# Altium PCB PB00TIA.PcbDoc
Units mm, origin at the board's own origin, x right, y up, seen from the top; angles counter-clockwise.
Board outline 90 x 50 mm, 4 copper layers (Top Layer, PWR, GND, Bottom Layer), stack 0.603 mm thick; 69 components, 34 nets, 213 pads, 160 vias.
Unrouted connection lines stored in the file: 4.
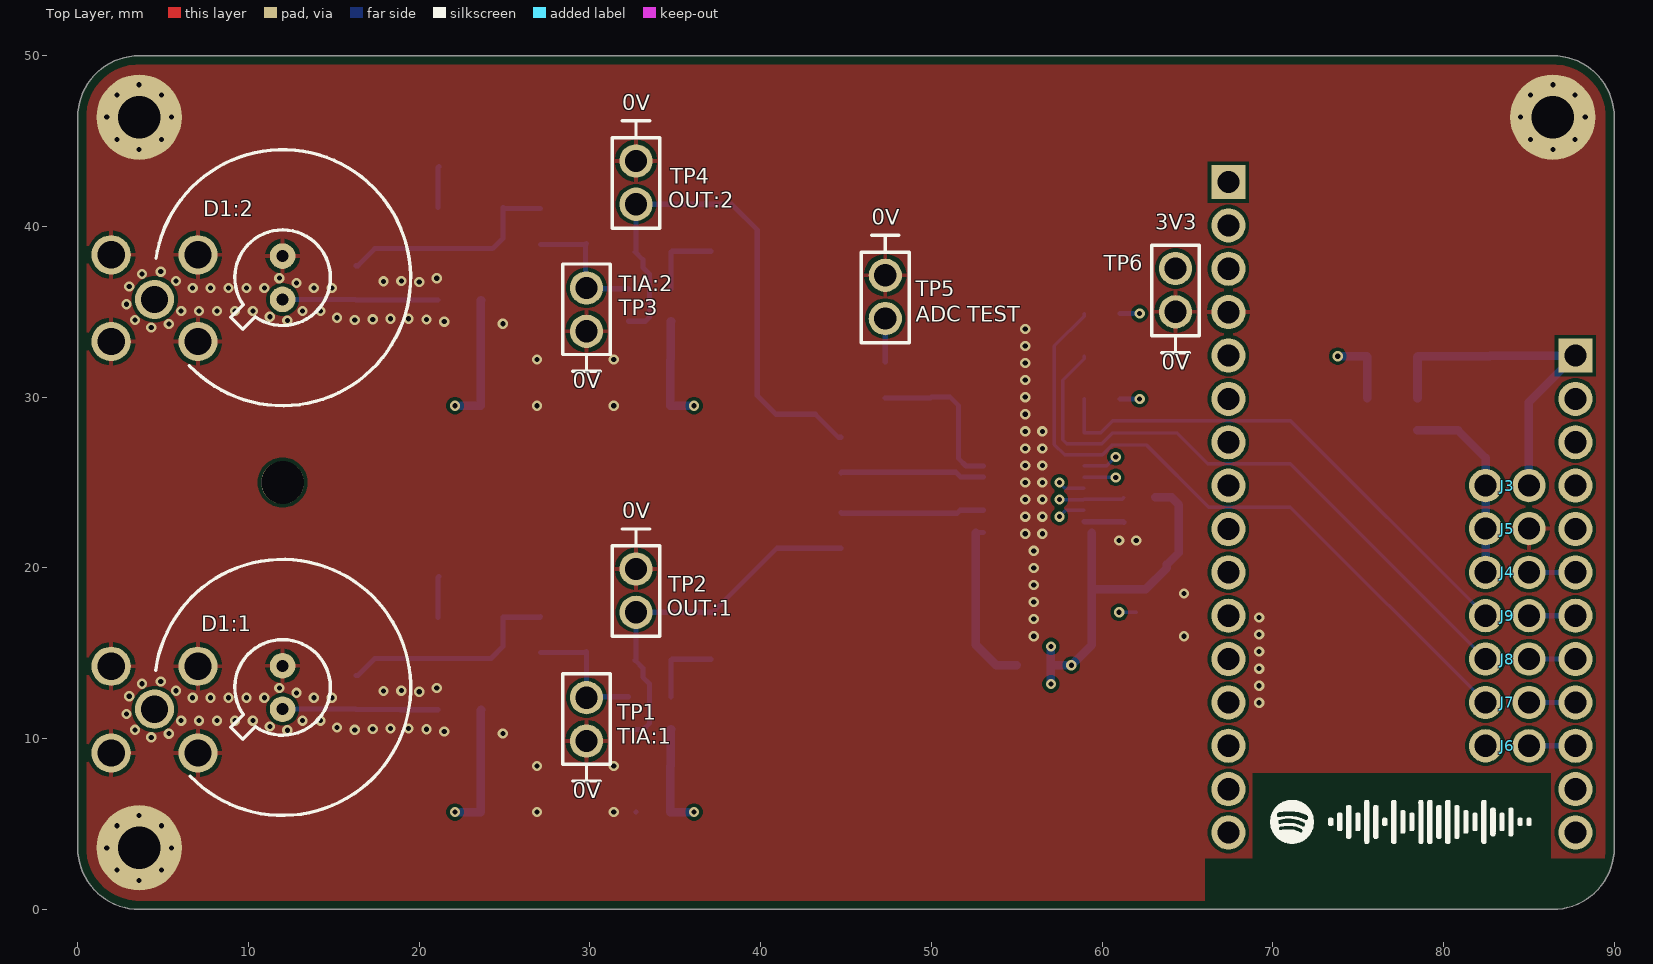
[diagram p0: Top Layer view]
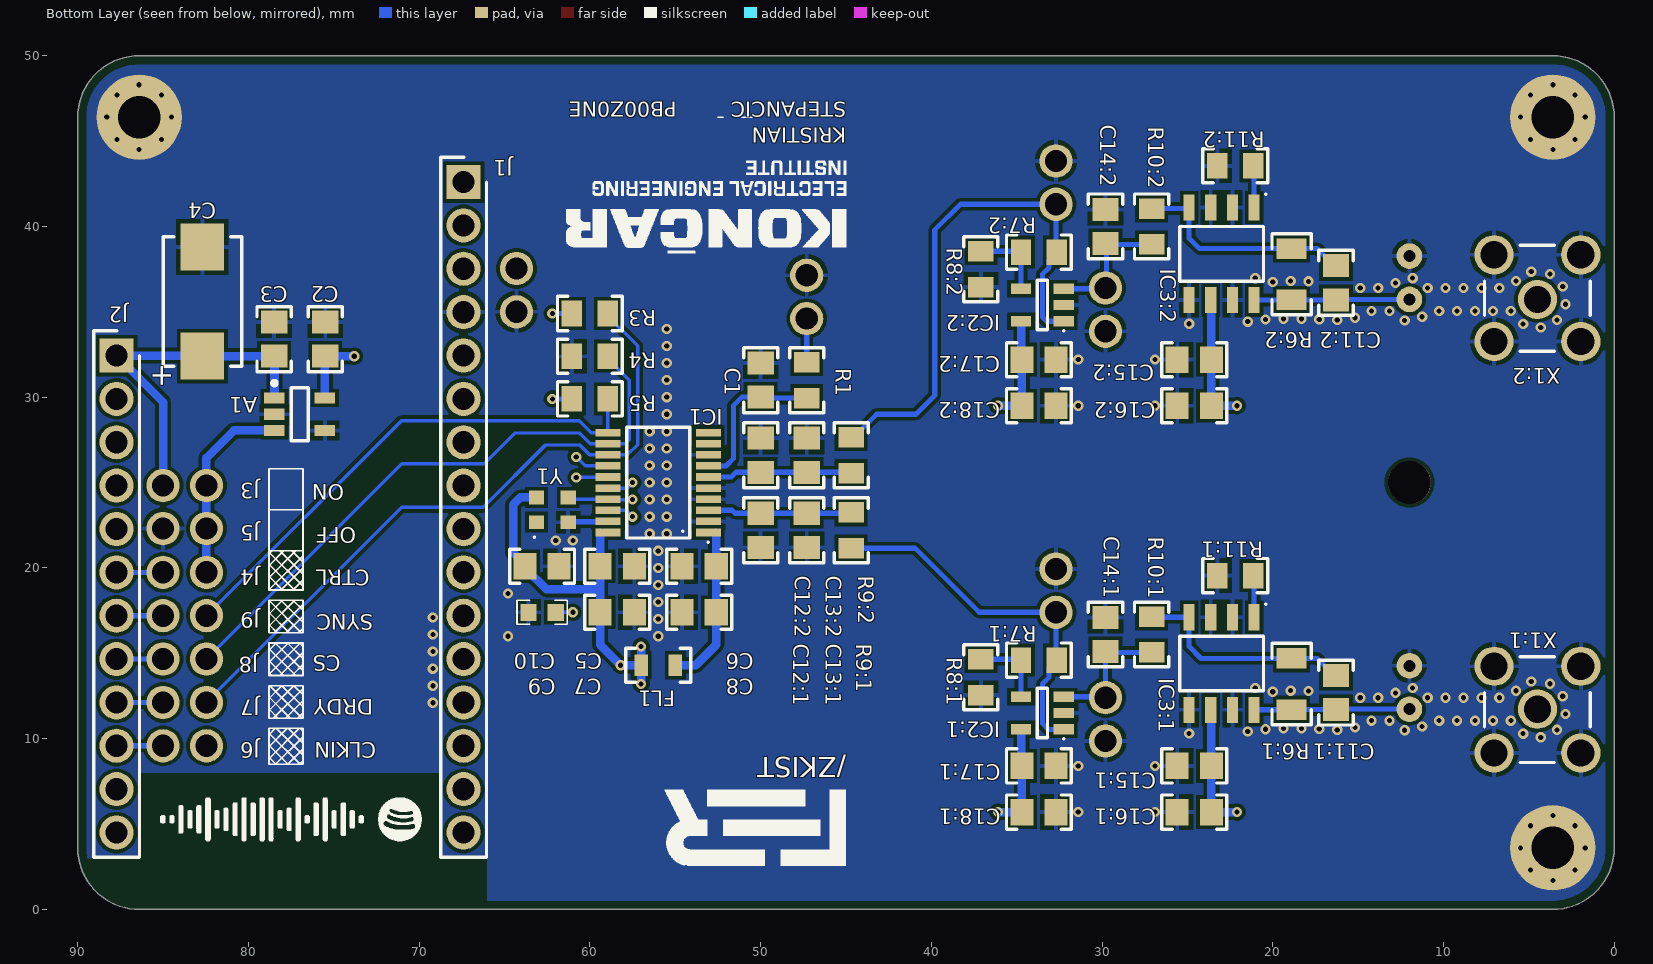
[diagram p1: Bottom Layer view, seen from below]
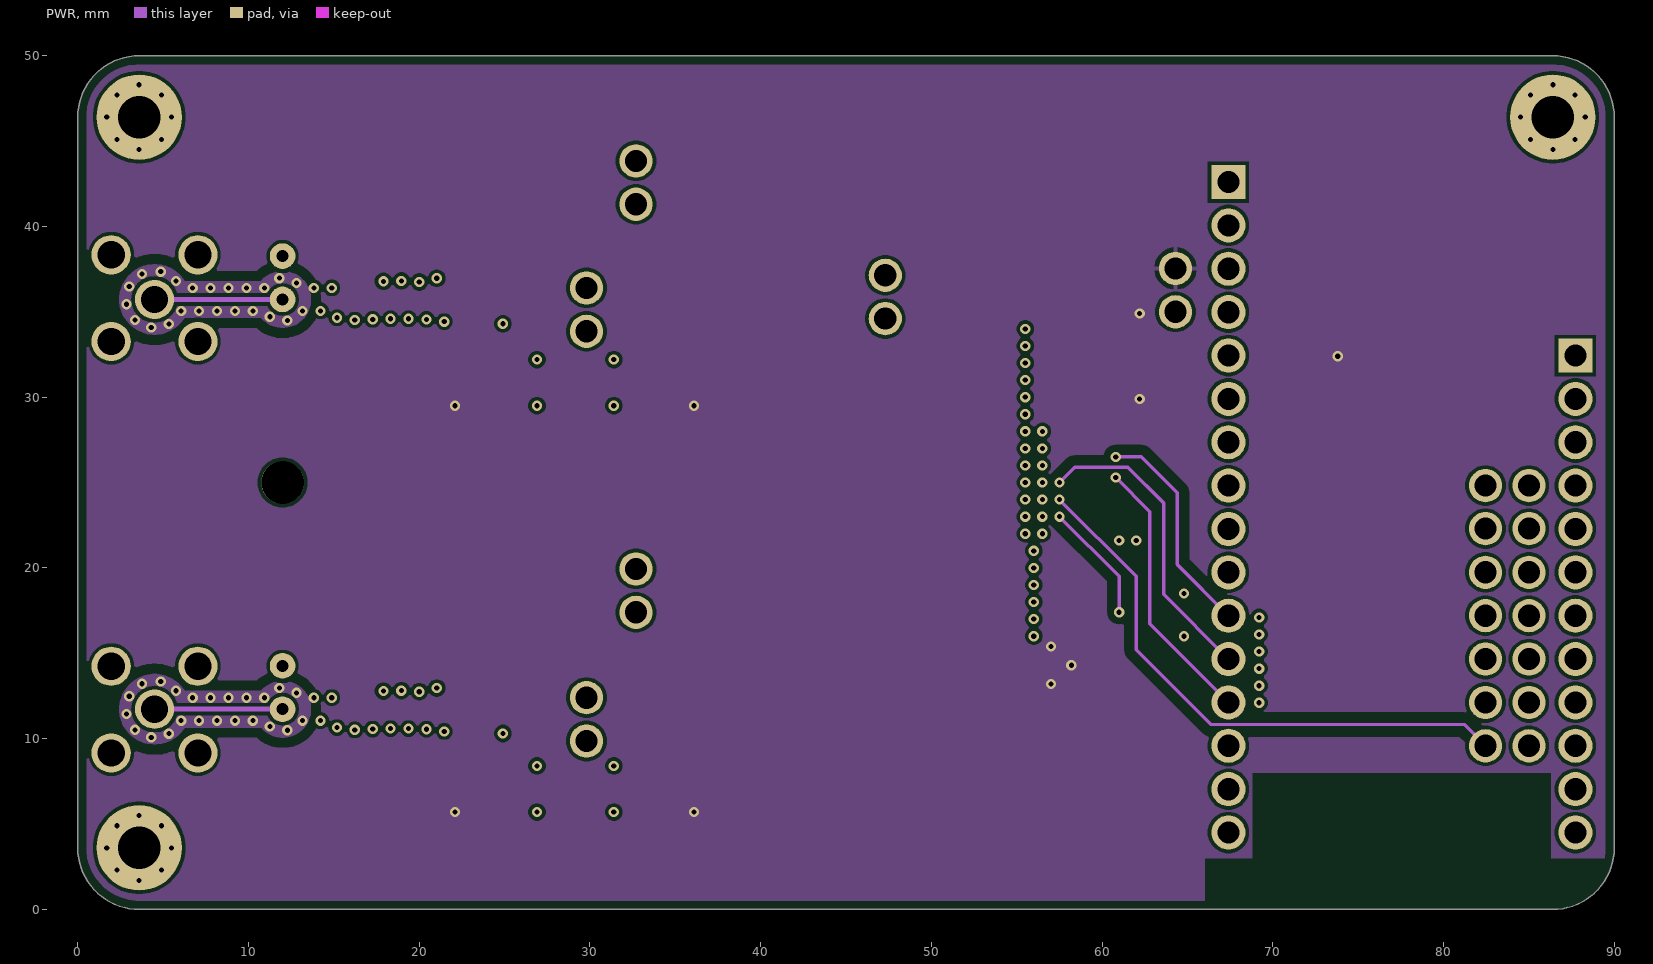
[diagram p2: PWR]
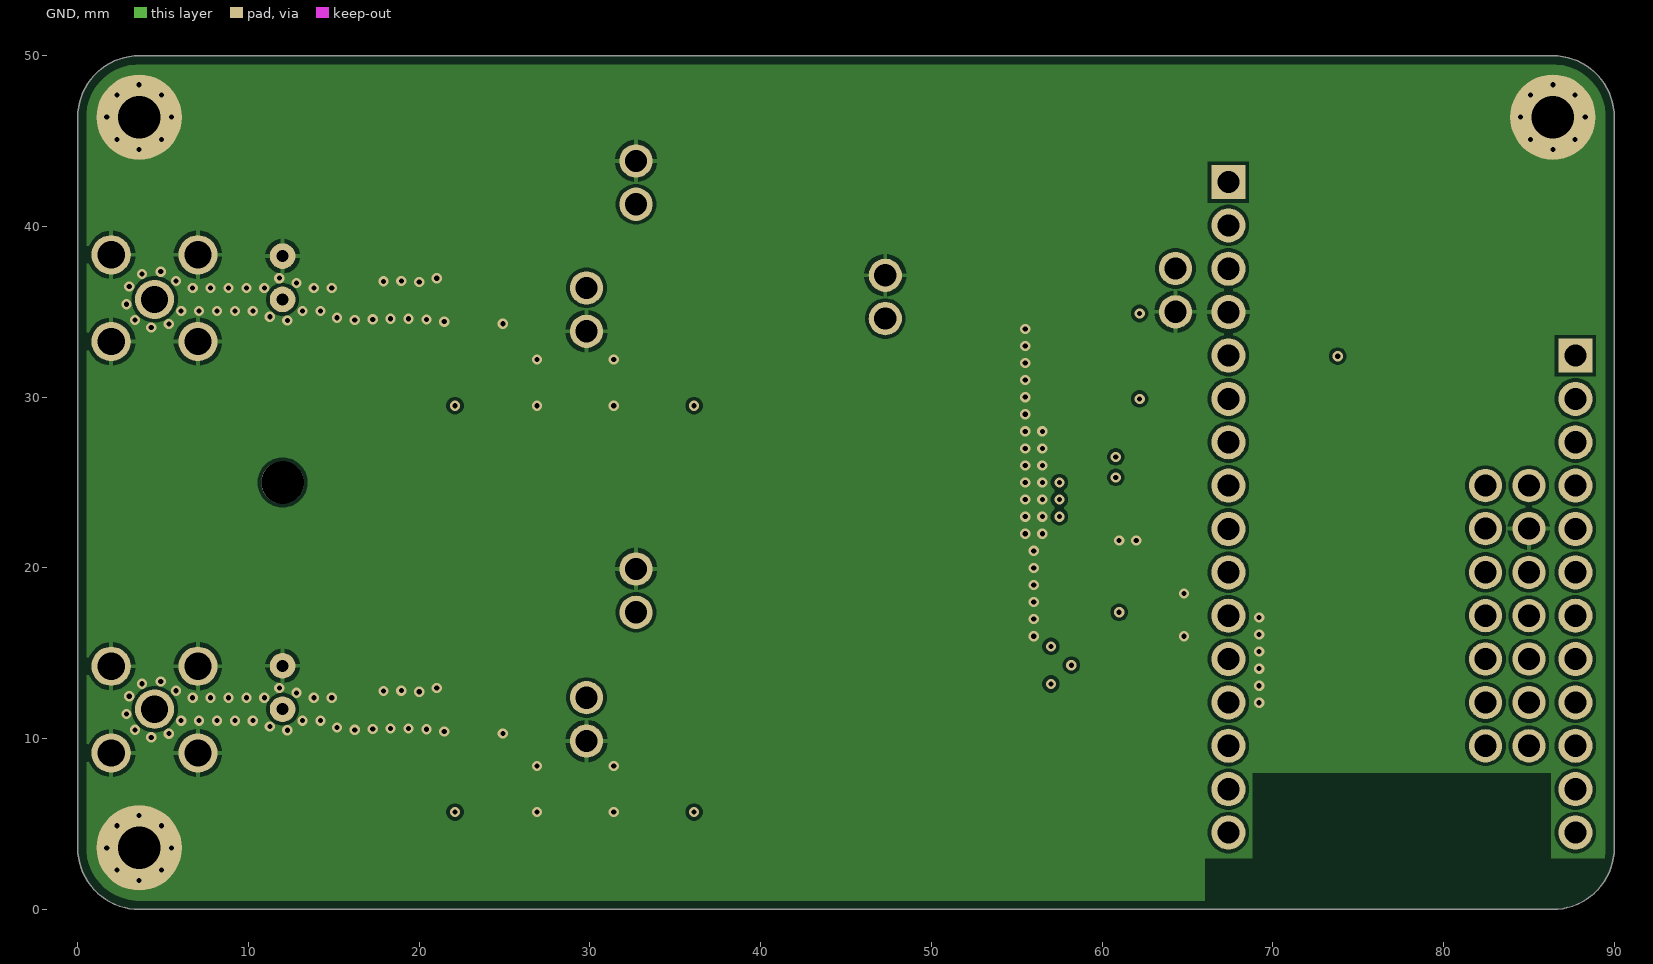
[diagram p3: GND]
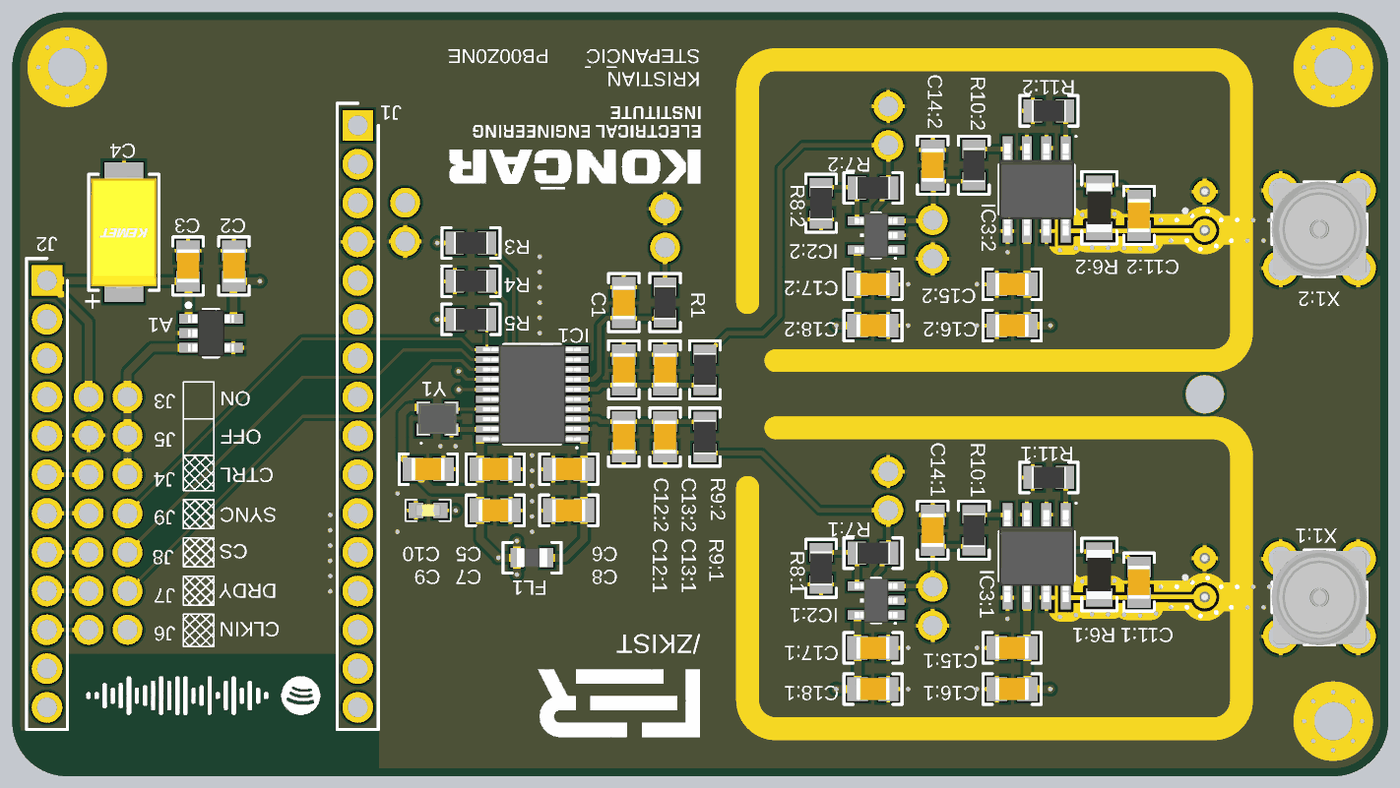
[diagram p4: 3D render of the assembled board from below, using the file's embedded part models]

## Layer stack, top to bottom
Top Solder: solder mask 0.0102, Solder Resist, Dk 3.5
Top Layer: signal copper 0.0356
Dielectric 2: prepreg 0.0711, PP-006, Dk 4.1
PWR: signal copper 0.035
Dielectric 1: dielectric 0.32, FR-4, Dk 4.8
GND: signal copper 0.035
Dielectric 3: prepreg 0.0711, PP-006, Dk 4.1
Bottom Layer: signal copper 0.0356
Bottom Solder: solder mask 0.0102, Solder Resist, Dk 3.5

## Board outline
0,3.6 0,46.4 cw(c3.6,46.4) 3.6,50 86.4,50 cw(c86.4,46.4) 90,46.4 90,3.6 cw(c86.4,3.6) 86.4,0 3.6,0 cw(c3.6,3.6)

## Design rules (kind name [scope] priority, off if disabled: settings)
BoardOutlineClearance [All] p1: gap=0.254 ignorepadtopadclearanceinfootprint=FALSE except(0: Arc-SplitContinuation Track-SplitContinuation SMDPad-SplitContinuation THPad-SplitContinuation Via-SplitContinuation Fill-SplitContinuation Poly-SplitContinuation Region-SplitContinuation Text-SplitContinuation; 0.508: Poly-OutlineEdge Poly-CavityEdge Poly-CutoutEdge Poly-SplitBarrior)
Clearance PWR [InNet('3V3') vs OnLayer('PWR')] p1: gap=0.6 ignorepadtopadclearanceinfootprint=TRUE
Clearance "Stitching 0V" [IsStitchingVia and InNet('0V') vs (IsVia and (Not IsStitchingVia)) Or IsPad] p2: gap=0.2 ignorepadtopadclearanceinfootprint=FALSE
Clearance [All] p3: gap=0.2 ignorepadtopadclearanceinfootprint=TRUE except(0.15: Arc-SMDPad Arc-THPad Track-SMDPad Track-THPad)
ComponentClearance [All] p1: gap=0.2 collisioncheckmode=3 verticalgap=0.2 showdistances=FALSE
HoleSize [All] p1: absolutevalues=TRUE maxlimit=10 minlimit=0.2 maxpercent=80.000 minpercent=20.000
HoleToHoleClearance [All] p1: gap=0.3 allowstackedmicrovias=TRUE
MinimumSolderMaskSliver MinimumSolderMaskSliver_1 [HasFootprint('SOT95P280X145-5M') vs HasFootprint('SOT95P280X145-5M')] p1: minsoldermaskwidth=0
MinimumSolderMaskSliver [All] p2: minsoldermaskwidth=0.1
PolygonConnect PolygonConnectVia [IsVia] p1: connectstyle=Direct reliefconductorwidth=0.254 reliefentries=4 polygonreliefangle="90 Angle" airgapwidth=0.254
PolygonConnect [All] p2: connectstyle=Relief reliefconductorwidth=0.254 reliefentries=4 polygonreliefangle="90 Angle" airgapwidth=0.254
RoutingVias [All] p1: holewidth=0.3 width=0.6 viastyle="Through Hole" minholewidth=0.3 minwidth=0.6 maxholewidth=0.3 maxwidth=0.6
SilkToSilkClearance [All] p1: silktosilkclearance=0.1
SilkToSolderMaskClearance [IsPad] p1: minsilkscreentomaskgap=0.1 clearancetoexposedcopper=TRUE
SolderMaskExpansion [All] p1: expansion=0.1 istentingtop=FALSE
SupplyNets "Schematic Supply Nets_4" [InNet('AVDD')] p1: voltage=0.000
SupplyNets "Schematic Supply Nets_3" [InNet('VBAT')] p2: voltage=0.000
SupplyNets "Schematic Supply Nets_2" [InNet('3V3')] p3: voltage=0.000
SupplyNets "Schematic Supply Nets_1" [InNet('0V')] p4: voltage=0.000
Width [All] p1: maxlimit=0.5 minlimit=0.2 preferedwidth=0.3
24 further rules are at their usual default settings.

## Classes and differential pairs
channel class TIA: U_TIA1 U_TIA2
component class UVSensor: A1 C1 C2 C3 C4 C? D? J1 J2 J3 J4 J5 J? R1 R? U?
component class U_TIA2: C11:2 C12:2 C13:2 C14:2 C15:2 C16:2 C17:2 C18:2 C?_U_TIA2 D1:2 D?_U_TIA2 FL?_U_TIA2 IC2:2 IC3:2 IC?_U_TIA2 R6:2 R7:2 R8:2 R9:2 R10:2 R11:2 R?_U_TIA2 X1:2 X?_U_TIA2
component class U_TIA1: C11:1 C12:1 C13:1 C14:1 C15:1 C16:1 C17:1 C18:1 C?_U_TIA1 C?_U_TIA2 D1:1 D?_U_TIA1 FL?_U_TIA1 FL?_U_TIA2 IC2:1 IC3:1 IC?_U_TIA1 R6:1 R7:1 R8:1 R9:1 R10:1 R11:1 R?_U_TIA1 X1:1 X?_U_TIA1
component class U_ADC: C5 C6 C7 C8 C9 C10 C? FL1 FL? IC1 IC? J6 J7 J8 J9 J? R3 R4 R5 R? Y1 Y?

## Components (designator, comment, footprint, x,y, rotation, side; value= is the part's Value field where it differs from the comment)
A1 "LP5907MFX-3.3/NOPB" SOT95P280X145-5M 77,29 r180 bottom value=LP5907MFX-3.3
C1 "10n" CAPC2012X14M 50,31 r90 bottom
C2 "1u" CAPC2012X14M 75.5,33.4 r90 bottom
C3 "1u" CAPC2012X14M 78.5,33.4 r90 bottom
C4 "TC_LESR_10u_35V_20%" CAPMP7343X31M 82.7,35.6 r90 bottom value=10u
C5 "0.1u" CAPC2012X14M 58.4,20.1 r180 bottom
C6 "0.1u" CAPC2012X14M 53.6,20.1 r0 bottom
C7 "1u" CAPC2012X14M 58.4,17.4 r180 bottom
C8 "1u" CAPC2012X14M 53.6,17.4 r0 bottom
C9 "220n" C_0603 62.8,17.4 r0 bottom
C10 "0.1u" CAPC2012X14M 62.8,20.1 r180 bottom
C11:1 "0.1n" CAPC2012X14M 16.3,12.7 r90 bottom (schematic designator C11)
C11:2 "0.1n" CAPC2012X14M 16.3,36.7 r90 bottom (schematic designator C11)
C12:1 "10n" CAPC2012X14M 50,22.2 r270 bottom (schematic designator C12)
C12:2 "10n" CAPC2012X14M 50,26.6 r90 bottom (schematic designator C12)
C13:1 "0.1u" CAPC2012X14M 47.3,22.2 r270 bottom (schematic designator C13)
C13:2 "0.1u" CAPC2012X14M 47.3,26.6 r90 bottom (schematic designator C13)
C14:1 "10n" CAPC2012X14M 29.8,16.1 r90 bottom (schematic designator C14)
C14:2 "10n" CAPC2012X14M 29.8,40 r90 bottom (schematic designator C14)
C15:1 "0.1u" CAPC2012X14M 24.6,8.4 r0 bottom (schematic designator C15)
C15:2 "0.1u" CAPC2012X14M 24.6,32.2 r0 bottom (schematic designator C15)
C16:1 "1u" CAPC2012X14M 24.6,5.7 r0 bottom (schematic designator C16)
C16:2 "1u" CAPC2012X14M 24.6,29.5 r0 bottom (schematic designator C16)
C17:1 "0.1u" CAPC2012X14M 33.7,8.4 r180 bottom (schematic designator C17)
C17:2 "0.1u" CAPC2012X14M 33.7,32.2 r180 bottom (schematic designator C17)
C18:1 "1u" CAPC2012X14M 33.7,5.7 r180 bottom (schematic designator C18)
C18:2 "1u" CAPC2012X14M 33.7,29.5 r180 bottom (schematic designator C18)
D1:1 "SG01S-18" TO18 12,11.725 r90 top (schematic designator D1)
D1:2 "SG01S-18" TO18 12,35.725 r90 top (schematic designator D1)
FL1 "BLM21SP601BH1D" BLM21AG102BH1J 56,14.3 r0 bottom
IC1 "ADS131M03IPWR" SOP65P640X120-20N 56,25 r0 bottom
IC2:1 "OPA387DBVT" SOT95P280X145-5N 33.5,11.5 r0 bottom (schematic designator IC2)
IC2:2 "OPA387DBVT" SOT95P280X145-5N 33.5,35.4 r0 bottom (schematic designator IC2)
IC3:1 "LMP7721MA" SOIC127P600X175-8N 23,14.4 r270 bottom (schematic designator IC3)
IC3:2 "LMP7721MA" SOIC127P600X175-8N 23,38.4 r270 bottom (schematic designator IC3)
J1 "61301611121" HDRV16W79P0X254_1X16_4064X254X874P 67.4,42.6 r270 bottom
J2 "61301211121" HDRV12W79P0X254_1X12_3048X254X874P 87.725,32.44 r270 bottom
J3 "61300211121" HDRV2W110P0X254_1X2_508X254X854P 82.46,24.82 r0 top
J4 "61300211121" HDRV2W110P0X254_1X2_508X254X854P 82.46,19.74 r0 top
J5 "61300211121" HDRV2W110P0X254_1X2_508X254X854P 82.46,22.3 r0 top
J6 "61300211121" HDRV2W110P0X254_1X2_508X254X854P 82.46,9.58 r0 top
J7 "61300211121" HDRV2W110P0X254_1X2_508X254X854P 82.46,12.12 r0 top
J8 "61300211121" HDRV2W110P0X254_1X2_508X254X854P 82.46,14.66 r0 top
J9 "61300211121" HDRV2W110P0X254_1X2_508X254X854P 82.46,17.2 r0 top
R1 "1K" RESC2112X05M 47.3,31 r270 bottom
R3 "10K" RESC2112X05M 60,34.9 r0 bottom
R4 "10K" RESC2112X05M 60,32.4 r0 bottom
R5 "10K" RESC2112X05M 60,29.9 r0 bottom
R6:1 "20M" RESC3216X76N 18.9,13.2 r90 bottom (schematic designator R6)
R6:2 "20M" RESC3216X76N 18.9,37.2 r90 bottom (schematic designator R6)
R7:1 "RES_4K7_0805_1%" RESC2112X05M 33.7,14.6 r180 bottom value=4K7 (schematic designator R7)
R7:2 "RES_4K7_0805_1%" RESC2112X05M 33.7,38.5 r180 bottom value=4K7 (schematic designator R7)
R8:1 "1K" RESC2112X05M 37.1,13.6 r90 bottom (schematic designator R8)
R8:2 "1K" RESC2112X05M 37.1,37.5 r90 bottom (schematic designator R8)
R9:1 "1K" RESC2112X05M 44.7,22.2 r90 bottom (schematic designator R9)
R9:2 "1K" RESC2112X05M 44.7,26.6 r270 bottom (schematic designator R9)
R10:1 "1K" RESC2112X05M 27.1,16.1 r270 bottom (schematic designator R10)
R10:2 "1K" RESC2112X05M 27.1,40 r270 bottom (schematic designator R10)
R11:1 "0R" RESC2112X05M 22.2,19.55 r180 bottom (schematic designator R11)
R11:2 "0R" RESC2112X05M 22.2,43.55 r180 bottom (schematic designator R11)
TP1 "61300211121" HDRV2W110P0X254_1X2_508X254X854P 29.8,9.86 r90 top
TP2 "61300211121" HDRV2W110P0X254_1X2_508X254X854P 32.7,17.4 r90 top
TP3 "61300211121" HDRV2W110P0X254_1X2_508X254X854P 29.8,33.86 r90 top
TP4 "61300211121" HDRV2W110P0X254_1X2_508X254X854P 32.7,43.84 r270 top
TP5 "61300211121" HDRV2W110P0X254_1X2_508X254X854P 47.3,37.14 r270 top
TP6 "61300211121" HDRV2W110P0X254_1X2_508X254X854P 64.3,37.54 r270 top
X1:1 "73251-3140" 73251-3140#1 4.5,11.7 r90 bottom (schematic designator X1)
X1:2 "73251-3140" 73251-3140#2 4.5,35.8 r270 bottom (schematic designator X1)
Y1 "ECS-2520MVLC-020-BN-TR" ECS2520MVLC020BNTR 62.2,23.4 r180 bottom

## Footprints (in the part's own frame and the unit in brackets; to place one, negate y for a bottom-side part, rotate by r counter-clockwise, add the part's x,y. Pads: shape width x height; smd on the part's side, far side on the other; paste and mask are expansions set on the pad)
73251-3140#1 [mm] "Connector, SMA, Receptacle, Vertical, THT, Molex"
  round 2.3 hole 1.6: 1(-2.54,-2.54) 1(-2.54,2.54) 1(2.54,-2.54) 1(2.54,2.54) 2(0.025,0)
  silkscreen extent -3.1,-3.1 3.1,3.1, body extent -3.13,-3.13 3.13,3.13, height 12.55
73251-3140#2 [mm] "Connector, SMA, Receptacle, Vertical, THT, Molex"
  round 2.3 hole 1.6: 1(-2.54,-2.54) 1(-2.54,2.54) 1(2.54,-2.54) 1(2.54,2.54) 2(0.075,0)
  silkscreen extent -3.1,-3.1 3.1,3.1, body extent -3.13,-3.13 3.13,3.13, height 12.55
BLM21AG102BH1J [mm]
  rect 0.8x1.25 smd: 1(-1,0) 2(1,0)
  silkscreen extent -1.9,-1 1.9,1, body extent -1,-0.63 1,0.63, height 0.85
C_0603 [mm]
  rect 0.95x1 smd: 1(-0.8,0) 2(0.8,0)
  silkscreen extent -1.48,-0.7 1.48,0.7, body extent -0.8,-0.4 0.8,0.4, height 0.81
CAPC2012X14M [mm] "Capacitor, 0805 (2012 metric), 2.0x1.25x1.4mm, Kemet"
  rect 1.35x1.55 smd: 1(-1,0) 2(1,0)
  silkscreen extent -1.9,-1 1.9,1, body extent -1.1,-0.72 1.1,0.72, height 1.4
CAPMP7343X31M [mm] "Molded Capacitor, 2-Leads, Body 7,30x4,30mm, IPC Low Density"
  rect 2.75x2.55 smd: 1(-3.2,0) 2(3.2,0)
  silkscreen extent -3.8,-2.3 3.8,2.3, body extent -3.65,-2.15 3.65,2.15, height 3.11
ECS2520MVLC020BNTR [mm]
  rect 0.9x0.8 smd: 1(-0.925,-0.725) 2(0.925,-0.725) 3(0.925,0.725) 4(-0.925,0.725)
  silkscreen extent -1.1,-1.65 -1,-1.55, body extent -1.3,-1.04 1.3,1.04, height 1
HDRV2W110P0X254_1X2_508X254X854P [mm]
  round 1.95 hole 1.3: 1(0,0) 2(2.54,0)
HDRV12W79P0X254_1X12_3048X254X874P [mm]
  rect 2x2 hole 1.3: 1(0,0)
  round 2 hole 1.3: 2(2.54,0) 3(5.08,0) 4(7.62,0) 5(10.16,0) 6(12.7,0) 7(15.24,0) 8(17.78,0) 9(20.32,0) 10(22.86,0) 11(25.4,0) 12(27.94,0)
  silkscreen extent -1.45,-1.35 29.39,1.35
HDRV16W79P0X254_1X16_4064X254X874P [mm]
  rect 2x2 hole 1.3: 1(0,0)
  round 2 hole 1.3: 2(2.54,0) 3(5.08,0) 4(7.62,0) 5(10.16,0) 6(12.7,0) 7(15.24,0) 8(17.78,0) 9(20.32,0) 10(22.86,0) 11(25.4,0) 12(27.94,0) 13(30.48,0) 14(33.02,0) 15(35.56,0) 16(38.1,0)
  silkscreen extent -1.45,-1.35 39.55,1.35
RESC2112X05M [mm] "Resistor, 0805 (2012 metric), 2.05x1.25x0.5mm, Vishay"
  rect 1.2x1.5 smd: 1(-1.05,0) 2(1.05,0)
  silkscreen extent -1.9,-1 1.9,1, body extent -1.1,-0.7 1.1,0.7, height 0.5
RESC3216X76N [mm]
  rect 1.2x1.75 smd: 1(-1.5,0) 2(1.5,0)
  silkscreen extent -2.37,-1.15 2.37,1.15, body extent -1.6,-0.8 1.6,0.8, height 0.76
SOIC127P600X175-8N [mm]
  rect 1.528x0.65 smd: 1(-2.711,1.905) 2(-2.711,0.635) 3(-2.711,-0.635) 4(-2.711,-1.905) 5(2.711,-1.905) 6(2.711,-0.635) 7(2.711,0.635) 8(2.711,1.905)
  silkscreen extent -3.47,-2.45 1.6,2.58, body extent -3.01,-2.45 3.01,2.45, height 1.63
SOP65P640X120-20N [mm]
  rect 1.475x0.45 smd: 1(-2.938,2.925) 2(-2.938,2.275) 3(-2.938,1.625) 4(-2.938,0.975) 5(-2.938,0.325) 6(-2.938,-0.325) 7(-2.938,-0.975) 8(-2.938,-1.625) 9(-2.938,-2.275) 10(-2.938,-2.925) 11(2.938,-2.925) 12(2.938,-2.275) 13(2.938,-1.625) 14(2.938,-0.975) 15(2.938,-0.325) 16(2.938,0.325) 17(2.938,0.975) 18(2.938,1.625) 19(2.938,2.275) 20(2.938,2.925)
  silkscreen extent -2.95,-3.25 1.85,3.51, body extent -3.2,-3.25 3.2,3.25, height 1.13
SOT95P280X145-5M [mm] "SOT23, 5-Leads, Body 2,90x2,80mm, Pitch 0,95mm, IPC Low Density"
  rect 1.2x0.65 smd: 1(-1.475,0.95) 2(-1.475,0) 3(-1.475,-0.95) 4(1.475,-0.95) 5(1.475,0.95)
  silkscreen extent -1.6,-1.55 0.5,1.95, body extent -1.5,-1.53 1.5,1.53, height 1.45
SOT95P280X145-5N [mm]
  rect 1.2x0.6 smd: 1(-1.25,0.95) 2(-1.25,0) 3(-1.25,-0.95) 4(1.25,-0.95) 5(1.25,0.95)
  silkscreen extent -1.27,-1.45 0.3,1.5, body extent -1.4,-1.45 1.4,1.45, height 1.2
TO18 [mm]
  round 1.5 hole 0.7: 1(2.54,0) 2(0,0)
  silkscreen extent -1.75,-2.8 4.07,3.03, body extent -1.73,-2.93 4.2,3.01, height 4.48

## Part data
A1: library part CMP-1291-0A, "LDO Voltage Regulators 250mA Ultra-Lo Noise LDO Reg", Manufacturer="Texas Instruments", OperatingTemp="-40C to +125C", PackageType=SOT-23-5, ValueNumeric=LP5907MFX-3.3, Voltage="2.2V to 5.5V"
C1 C12:1 C12:2 C14:1 C14:2: library part CAPC2012X14M, "C0805H103K5GACTU,  / Multilayer Ceramic Capacitors MLCC - SMD/SMT 50V 0.01uF C0G 0805 10%"
C2 C3 C7 C8 C16:1 C16:2 C18:1 C18:2: library part CAPC2012X14M, "C0805C105K5RACTU, Multilayer Ceramic Capacitors MLCC - SMD/SMT 50V 1uF X7R 0805 10%"
C4: library part CMP-0312-0D, "Capacitor, Tantalum, 10uF, 35V, 20%, Low ESR, 250mΩ, Kemet", Manufacturer=Kemet, ManufacturerPartNumber=T495D106M035ATE250, OperatingTemp="-55 to 125", PackageType=7343-31, Tolerance=20%, ValueNumeric=10000000, Voltage=35V
C5 C6 C10 C13:1 C13:2 C15:1 C15:2 C17:1 C17:2: library part CAPC2012X14M, "C0805C104K5RACTU, Multilayer Ceramic Capacitors MLCC - SMD/SMT 50V 0.1uF X7R 0805 10%"
C9: library part CAP_0603, "Capacitor 0603"
C11:1 C11:2: library part CAPC2012X14M, "C0805C101J5GAC3123,  / Multilayer Ceramic Capacitors MLCC - SMD/SMT 50V 100pF C0G 0805 5%"
D1:1 D1:2: library part SG01-TO18, "SG01 series photodiode, TO18 housing"
FL1: "BLM18PG181SN1D", Manufacturer_Name="Murata Electronics", Mouser Part Number=81-BLM21SP601BH1D
IC1: "Integrated Circuit", Manufacturer_Name="Texas Instruments", Mouser Part Number=595-ADS131M03IPWR
IC2:1 IC2:2: "Integrated Circuit", Manufacturer_Name="Texas Instruments", Mouser Part Number=595-OPA387DBVT
IC3:1 IC3:2: "Integrated Circuit", Manufacturer_Name="Texas Instruments", Mouser Part Number=N/A
J1: "Connector", Manufacturer_Name="Wurth Elektronik", Mouser Part Number=710-61301611121
J2: "Connector", Manufacturer_Name="Wurth Elektronik", Mouser Part Number=710-61301211121
J3 J4 J5 J6 J7 J8 J9 TP1 TP2 TP3 TP4 TP5 TP6: "Connector", Manufacturer_Name="Wurth Elektronik", Mouser Part Number=710-61300211121
R1 R8:1 R8:2 R9:1 R9:2 R10:1 R10:2: library part RESC2112X05M, "CRCW08051K00JNEC, Thick Film Resistors D12/CRCW0805 200 1K0 5% ET6 e3"
R3 R4 R5: library part RESC2112X05M, "CRCW080510K0FKEA, Thick Film Resistors 1/8watt 10Kohms 1% 100ppm"
R6:1 R6:2: library part RESC3216X76N, "CRHV1206AF20M0FKFT / Thick Film Resistors 20Mohms 1% 100ppm 0.3watt 3-side term"
R7:1 R7:2: library part CMP-0039-0H, "Resistor, Thick Film, 4K7, 1%, 0.125W, TK100, Vishay", Manufacturer=Vishay, ManufacturerPartNumber=CRCW08054K70FKEA, OperatingTemp="- 55C to +155C", PackageType=0805, Power=0.125W, Tolerance=1%, ValueNumeric=4700
R11:1 R11:2: library part RESC2112X05M
X1:1 X1:2: library part CMP-1058-0A, "Connector, Receptacle, SMA, RF, 50Ohm, Molex", Manufacturer=Molex, OperatingTemp="-65C to +165C", PackageType=SMA
Y1: "ECS-2520MVLC-081.92-BN-TR, Standard Clock Oscillators MultiVolt ECS-2520MVLC,Active,XO (Standard),8.192MHz,Enable/Disable,CMOS,1.8V, 2.5V, 3.3V,+/-50ppm,-40 C 85 C,Surface Mount,4-SMD, No Lead,0.098\" L x 0.079\" W (2.50mm x 2.00mm),0.035\" (0.90mm)", Manufacturer_Name=ECS, Mouser Part Number=520-2520MVLC-020BNTR

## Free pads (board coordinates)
  round 2.5 hole 2.5 mask+0.1: 0(12,25)
  round 5 hole 2.5: H4(3.6,3.6) H4(3.6,46.4) H4(86.4,46.4)

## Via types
v1: diameter 0.6, hole 0.3, Top Layer to Bottom Layer, tented both sides, 160 vias

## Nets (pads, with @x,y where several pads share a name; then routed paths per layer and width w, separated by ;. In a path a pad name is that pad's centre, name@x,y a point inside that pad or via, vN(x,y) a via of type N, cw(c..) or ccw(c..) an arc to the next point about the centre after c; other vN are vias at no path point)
0V: A1.2 A1.4 C1.2 C2.2 C3.2 C4.2 C5.2 C6.2 C7.2 C8.2 C9.2 C10.2 C12:1.2 C12:2.2 C13:1.2 C13:2.2 C14:1.2 C14:2.2 C15:1.2 C15:2.2 C16:1.2 C16:2.2 C17:1.2 C17:2.2 C18:1.2 C18:2.2 D1:1.1 D1:2.1 IC1.2 IC1.4 IC1.5 IC1.8 IC1.19 IC2:1.2 IC2:2.2 IC3:1.2 IC3:1.3 IC3:1.5 IC3:1.7 IC3:2.2 IC3:2.3 IC3:2.5 IC3:2.7 J1.4 J5.2 pad.H4 R4.2 R8:1.1 R8:2.1 R11:1.1 R11:2.1 TP1.1 TP2.2 TP3.1 TP4.1 TP5.1 TP6.2 X1:1.1 X1:2.1 Y1.2 | length 2.4
  Bottom Layer w0.3: IC1.19 58.963,22.7 61.25,22.7 Y1.2
  other v1: 3.6,1.7 2.3,2.3 4.9,2.3 1.7,3.6 5.5,3.6 2.3,4.9 4.9,4.9 3.6,5.5 26.9,5.7 31.4,5.7 26.9,8.4 31.4,8.4 4.309,10.076 5.337,10.29 24.9,10.3 21.469,10.425 3.356,10.516 12.279,10.495 16.229,10.515 17.278,10.559 20.427,10.553 18.328,10.59 19.378,10.59 15.188,10.649 11.252,10.711 6.059,11.053 7.109,11.053 8.159,11.053 9.209,11.053 10.259,11.053 13.168,11.053 14.218,11.053 2.863,11.443 69.2,12.1 6.731,12.397 7.781,12.397 8.831,12.397 9.881,12.397 10.931,12.397 13.831,12.397 14.881,12.397 3.017,12.482 12.821,12.683 20.004,12.748 17.906,12.786 5.764,12.805 18.956,12.81 11.811,12.971 21.032,12.963 69.2,13.1 3.766,13.217 4.867,13.351 69.2,14.1 69.2,15.1 56,16 64.8,16 69.2,16.1 56,17 69.2,17.1 56,18 64.8,18.5 56,19 56,20 56,21 61,21.6 62,21.6 55.5,22 56.5,22 55.5,23 56.5,23 55.5,24 56.5,24 55.5,25 56.5,25 55.5,26 56.5,26 55.5,27 56.5,27 55.5,28 56.5,28 55.5,29 26.9,29.5 31.4,29.5 55.5,30 55.5,31 55.5,32 26.9,32.2 31.4,32.2 55.5,33 55.5,34 4.309,34.076 5.337,34.29 24.9,34.3 21.469,34.425 12.279,34.495 3.356,34.516 16.229,34.515 17.278,34.559 20.427,34.553 18.328,34.59 19.378,34.59 15.188,34.649 11.252,34.711 6.059,35.053 7.109,35.053 8.159,35.053 9.209,35.053 10.259,35.053 13.168,35.053 14.218,35.053 2.863,35.443 6.731,36.397 7.781,36.397 8.831,36.397 9.881,36.397 10.931,36.397 13.831,36.397 14.881,36.397 3.017,36.482 12.821,36.683 20.004,36.748 5.764,36.805 17.906,36.786 18.956,36.81 11.811,36.971 21.032,36.963 3.766,37.217 4.867,37.351 3.6,44.5 86.4,44.5 2.3,45.1 4.9,45.1 85.1,45.1 87.7,45.1 1.7,46.4 5.5,46.4 84.5,46.4 88.3,46.4 2.3,47.7 4.9,47.7 85.1,47.7 87.7,47.7 3.6,48.3 86.4,48.3
3V3: A1.5 C2.1 C5.1 C7.1 C10.1 C15:1.1 C15:2.1 C16:1.1 C16:2.1 C17:1.1 C17:2.1 C18:1.1 C18:2.1 FL1.2 IC1.20 IC2:1.5 IC2:2.5 IC3:1.6 IC3:2.6 R3.2 R5.2 TP6.1 Y1.4 | length 56.4
  Bottom Layer w0.3: R5.2 v1(62.2,29.9) ; R3.2 v1(62.2,34.9)
  Bottom Layer w0.5: v1(22.1,5.7) C16:1.1 C15:1.1 23.617,8.418 23.617,11.672 IC3:1.6 ; v1(22.1,29.5) C16:2.1 C15:2.1 23.617,32.217 23.617,35.671 IC3:2.6 ; IC2:1.5 34.725,10.525 34.725,8.412 34.7,8.387 C18:1.1 v1(36.1,5.7) ; IC2:2.5 34.725,34.425 34.725,32.225 C17:2.1 C18:2.1 v1(36.1,29.5) ; v1(57,13.2) FL1.2 ; v1(57,15.4) FL1.2 ; IC1.20@59.4,22.05 C5.1 59.4,18.75 ; Y1.4 64.075,24.125 64.5,23.7 64.5,20.9 63.8,20.2 C10.1 63.8,20 62.55,18.75 59.4,18.75 ; v1(73.8,32.4) C2.1 75.525,32.375 A1.5 ; FL1.2 v1(58.2,14.3) 59.4,15.5 C7.1 59.4,18.75
ADC_TEST: R1.1 TP5.2 | length 2.5
  Bottom Layer w0.3: R1.1 TP5.2
AVDD: C6.1 C8.1 FL1.1 IC1.1 | length 9.9
  Bottom Layer w0.3: IC1.1@52.625,22.075 IC1.1
  Bottom Layer w0.5: IC1.1@52.6,22.05 C6.1 C8.1 52.6,15.5 53.8,14.3 FL1.1
D5: J2.10 J6.2 | length 2.7
  Bottom Layer w0.3: J6.2 J2.10
D6: J2.9 J7.2 | length 2.7
  Bottom Layer w0.3: J7.2 J2.9
D9: J2.8 J8.2 | length 2.7
  Bottom Layer w0.3: J8.2 J2.8
D10: J2.7 J9.2 | length 2.7
  Bottom Layer w0.3: J9.2 J2.7
D11: J2.6 J4.2 | length 2.7
  Bottom Layer w0.3: J4.2 J2.6
MISO: IC1.15 J1.13 | length 17.8
  PWR w0.2: v1(60.8,25.3) 62.8,23.3 62.8,16.72 J1.13
  Bottom Layer w0.2: IC1.15 58.951,25.312 60.788,25.312 v1(60.8,25.3)
MOSI: IC1.16 J1.12 | length 19.6
  PWR w0.2: v1(57.5,25) 58.4,25.9 61.5,25.9 63.6,23.8 63.6,18.46 J1.12
  Bottom Layer w0.2: v1(57.5,25) 57.825,24.675 IC1.16
NetA1_3: A1.3 J3.1 J4.1 J5.1 | length 11.4
  Bottom Layer w0.5: A1.3 80.85,28.05 82.46,26.44 J3.1 J5.1 J4.1
NetC1_1: C1.1 IC1.7 R1.2 | length 9.3
  Bottom Layer w0.3: R1.2 49.95,29.95 C1.1 51.1,30 51.6,29.5 51.6,26.4 52.025,25.975 IC1.7
NetC9_1: C9.1 IC1.18 | length 9.6
  PWR w0.2: v1(57.5,23) 61,19.5 v1(61,17.4)
  Bottom Layer w0.2: v1(57.5,23) 57.875,23.375 IC1.18 ; v1(61,17.4) C9.1
NetC11:1_1: C11:1.1 D1:1.2 IC3:1.8 R6:1.1 X1:1.2 | length 16.6
  PWR w0.3: X1:1.2 D1:1.2
  Bottom Layer w0.3: D1:1.2 16.275,11.725 C11:1.1 R6:1.1 18.911,11.689 IC3:1.8
NetC11:1_2: C11:1.2 IC3:1.4 R6:1.2 R10:1.1 | length 13.2
  Bottom Layer w0.3: C11:1.2 16.4,13.7 17.4,14.7 24.2,14.7 24.905,15.405 IC3:1.4 27.061,17.111 R10:1.1
NetC11:2_1: C11:2.1 D1:2.2 IC3:2.8 R6:2.1 X1:2.2 | length 16.6
  PWR w0.3: X1:2.2 D1:2.2
  Bottom Layer w0.3: D1:2.2 16.275,35.725 C11:2.1 R6:2.1 18.911,35.689 IC3:2.8
NetC11:2_2: C11:2.2 IC3:2.4 R6:2.2 R10:2.1 | length 13.3
  Bottom Layer w0.3: C11:2.2 16.4,37.7 17.4,38.7 R6:2.2 24.3,38.7 24.905,39.305 IC3:2.4 24.966,41.05 R10:2.1 R10:2.1@27.111,41.061
NetC12:1_1: C12:1.1 C13:1.1 IC1.3 R9:1.2 | length 8.5
  Bottom Layer w0.3: R9:1.2 44.75,23.2 C13:1.1 C12:1.1 51.5,23.2 51.675,23.375 IC1.3
NetC12:2_1: C12:2.1 C13:2.1 IC1.6 R9:2.2 | length 8.5
  Bottom Layer w0.3: R9:2.2 44.75,25.6 51.45,25.6 51.725,25.325 IC1.6
NetC14:1_1: C14:1.1 IC2:1.3 R10:1.2 TP1.2 | length 7.9
  Bottom Layer w0.3: R10:1.2 29.75,15.05 C14:1.1 TP1.2 29.85,12.45 IC2:1.3
NetC14:2_1: C14:2.1 IC2:2.3 R10:2.2 TP3.2 | length 7.8
  Bottom Layer w0.3: R10:2.2 C14:2.1@29.75,38.95 ; IC2:2.3 29.85,36.35 TP3.2 29.75,36.45 C14:2.1@29.75,38.95 ; C14:2.1@29.75,38.95 C14:2.1 C14:2.1@29.75,38.95
NetIC1_11: IC1.11 J9.1 R5.1 | length 30.5
  Bottom Layer w0.2: IC1.11 59.925,27.925 60.625,28.625 71.035,28.625 J9.1 ; IC1.11@58.95,27.937 R5.1
NetIC1_12: IC1.12 J8.1 R4.1 | length 36
  Bottom Layer w0.2: R4.1 58.95,32.25 57.7,31 57.7,27.5 57.925,27.275 IC1.12 59.975,27.275 60.6,27.9 64.4,27.9 66.2,26.1 71.02,26.1 J8.1
NetIC1_13: IC1.13 J7.1 R3.1 | length 40.4
  Bottom Layer w0.2: R3.1 58.95,34.75 57.2,33 57.2,27.226 57.801,26.625 IC1.13 60.025,26.625 60.6,27.2 62.6,27.2 66.25,23.55 71.03,23.55 J7.1
NetIC1_17: IC1.17 J6.1 Y1.3 | length 37.3
  PWR w0.2: v1(57.5,24) 62,19.5 62,15.2 66.37,10.83 81.21,10.83 J6.1
  Bottom Layer w0.2: v1(57.5,24) 58.913,24 IC1.17 61.175,24.025 Y1.3
NetIC2:1_1: IC2:1.1 R7:1.2 R9:1.1 TP2.1 | length 21.8
  Bottom Layer w0.3: IC2:1.1@32.25,10.537 33.137,10.537 33.5,10.9 33.5,13.2 33.1,13.6 33.1,14.137 R7:1.2@32.65,14.587 ; R7:1.2 32.7,14.65 TP2.1 37.2,17.4 40.95,21.15 R9:1.1
NetIC2:1_4: IC2:1.4 R7:1.1 R8:1.2 | length 4.5
  Bottom Layer w0.3: IC2:1.4 R7:1.1 34.8,14.65 R8:1.2
NetIC2:2_1: IC2:2.1 R7:2.2 R9:2.1 TP4.2 | length 31.7
  Bottom Layer w0.3: IC2:2.1 33.25,34.45 33.5,34.7 33.5,37.2 33.1,37.6 33.1,38.05 R7:2.2 32.7,38.55 TP4.2 38.3,41.3 39.8,39.8 39.8,30.1 40.9,29 43.2,29 44.55,27.65 R9:2.1
NetIC2:2_4: IC2:2.4 R7:2.1 R8:2.2 | length 4.5
  Bottom Layer w0.3: IC2:2.4 R7:2.1 34.8,38.55 R8:2.2
NetIC3:1_1: IC3:1.1 R11:1.2 | length 2.4
  Bottom Layer w0.3: IC3:1.1 21.095,19.445 R11:1.2@21.15,19.5
NetIC3:2_1: IC3:2.1 R11:2.2 | length 2.4
  Bottom Layer w0.3: IC3:2.1 21.095,43.445 R11:2.2@21.15,43.5
SCLK: IC1.14 J1.11 | length 15
  PWR w0.2: v1(60.8,26.5) 62.3,26.5 64.4,24.4 64.4,20.2 J1.11
  Bottom Layer w0.2: IC1.14 60.275,25.975 v1(60.8,26.5)
VBAT: A1.1 C3.1 C4.1 J2.1 J3.2 | length 20.5
  Bottom Layer w0.5: A1.1 78.475,32.375 C3.1 C4.1 82.74,32.44 J2.1 85,29.715 J3.2
pads on no net: IC1.9 IC1.10 J1.1 J1.2 J1.3 J1.5 J1.6 J1.7 J1.8 J1.9 J1.10 J1.14 J1.15 J1.16 J2.2 J2.3 J2.4 J2.5 J2.11 J2.12 Y1.1

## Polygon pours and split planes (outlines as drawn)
0V on Bottom Solder (solid): 9.6,10.8 10.735,10.8 10.761,10.774 10.821,10.696 10.971,10.546 11.127,10.426 11.205,10.381 11.311,10.32 11.493,10.244 11.698,10.189 11.894,10.163 12.106,10.163 12.302,10.189 12.507,10.244 12.689,10.32 12.873,10.426 13.029,10.546 13.179,10.696 13.263,10.805 14.745,10.805 14.822,10.619 14.951,10.451 15.119,10.322 15.315,10.241 15.525,10.213 17.075,10.213 17.285,10.241 17.481,10.322 17.599,10.412 17.619,10.397 17.815,10.316 18.025,10.288 19.775,10.288 19.985,10.316 20.165,10.39 20.196,10.351 20.364,10.222 20.56,10.141 20.77,10.113 21.42,10.113 21.63,10.141 21.826,10.222 21.994,10.351 22.123,10.519 22.204,10.715 22.232,10.925 22.232,12.453 22.204,12.663 22.123,12.859 21.994,13.027 21.826,13.156 21.63,13.237 21.42,13.265 20.77,13.265 20.56,13.237 20.364,13.156 20.196,13.027 20.178,13.004 19.985,13.084 19.775,13.112 18.025,13.112 17.815,13.084 17.619,13.003 17.354,12.8 13.133,12.8 13.029,12.904 12.873,13.024 12.795,13.069 12.689,13.13 12.507,13.206 12.302,13.261 12.106,13.287 11.894,13.287 11.698,13.261 11.493,13.206 11.311,13.13 11.127,13.024 10.971,12.904 10.821,12.754 10.761,12.676 9.624,12.676 9.6,12.7
0V on Bottom Solder (solid): 9.6,34.8 10.735,34.8 10.761,34.774 10.821,34.696 10.971,34.546 11.127,34.426 11.205,34.381 11.311,34.32 11.493,34.244 11.698,34.189 11.894,34.163 12.106,34.163 12.302,34.189 12.507,34.244 12.689,34.32 12.873,34.426 13.029,34.546 13.179,34.696 13.263,34.805 14.745,34.805 14.822,34.619 14.951,34.451 15.119,34.322 15.315,34.241 15.525,34.213 17.075,34.213 17.285,34.241 17.481,34.322 17.599,34.412 17.619,34.397 17.815,34.316 18.025,34.288 19.775,34.288 19.985,34.316 20.165,34.39 20.196,34.351 20.364,34.222 20.56,34.141 20.77,34.113 21.42,34.113 21.63,34.141 21.826,34.222 21.994,34.351 22.123,34.519 22.204,34.715 22.232,34.925 22.232,36.453 22.204,36.663 22.123,36.859 21.994,37.027 21.826,37.156 21.63,37.237 21.42,37.265 20.77,37.265 20.56,37.237 20.364,37.156 20.196,37.027 20.178,37.004 19.985,37.084 19.775,37.112 18.025,37.112 17.815,37.084 17.619,37.003 17.354,36.8 13.133,36.8 13.029,36.904 12.873,37.024 12.795,37.069 12.689,37.13 12.507,37.206 12.302,37.261 12.106,37.287 11.894,37.287 11.698,37.261 11.493,37.206 11.311,37.13 11.127,37.024 10.971,36.904 10.821,36.754 10.761,36.676 9.624,36.676 9.6,36.7
0V on Bottom Solder "NONET_L-01_P-001" (solid): 2.463,11.725 ccw(c4.5,11.725) 4.5,9.688 ccw(c4.5,11.725) 6.537,11.725 ccw(c4.5,11.725) 4.5,13.762 ccw(c4.5,11.725)
0V on Bottom Solder "NONET_L-01_P-001" (solid): 2.463,35.725 ccw(c4.5,35.725) 4.5,33.688 ccw(c4.5,35.725) 6.537,35.725 ccw(c4.5,35.725) 4.5,37.762 ccw(c4.5,35.725)
no net on Bottom Overlay "NONET_L-01_P-001" (hatched 45Degree grid 0.5 track 0.1): 78.8,18.7 76.8,18.7 76.8,21 78.8,21
no net on Bottom Overlay "NONET_L-01_P-001" (hatched 45Degree grid 0.5 track 0.1): 78.8,8.495 76.8,8.495 76.8,10.6 78.8,10.6
no net on Bottom Overlay "NONET_L-01_P-001" (hatched 45Degree grid 0.5 track 0.1): 78.8,11.2 76.8,11.2 76.8,13.1 78.8,13.1
no net on Bottom Overlay "NONET_L-01_P-001" (hatched 45Degree grid 0.5 track 0.1): 78.8,13.7 76.8,13.7 76.8,15.6 78.8,15.6
no net on Bottom Overlay "NONET_L-01_P-001" (hatched 45Degree grid 0.5 track 0.1): 78.8,16.2 76.8,16.2 76.8,18.1 78.8,18.1
3V3 on PWR "3V3_L02_P103" (solid, pour order 103): 0,0 90,0 90,50 0,50
0V on PWR "PWR-0V 2" (solid, pour order 100): 217 vertices, not listed, extent 2.435,9.66 13.662,13.79
0V on PWR "PWR-0V 2" (solid, pour order 80): 217 vertices, not listed, extent 2.435,33.66 13.662,37.79
0V on Top Solder "NONET_L-01_P-001" (solid): 2.463,11.725 ccw(c4.5,11.725) 4.5,9.688 ccw(c4.5,11.725) 6.537,11.725 ccw(c4.5,11.725) 4.5,13.762 ccw(c4.5,11.725)
0V on Top Solder "NONET_L-01_P-001" (solid): 10.454,11.725 ccw(c12,11.725) 12,10.179 ccw(c12,11.725) 13.546,11.725 ccw(c12,11.725) 12,13.271 ccw(c12,11.725)
0V on Top Solder "NONET_L-01_P-001" (solid): 10.454,35.725 ccw(c12,35.725) 12,34.179 ccw(c12,35.725) 13.546,35.725 ccw(c12,35.725) 12,37.271 ccw(c12,35.725)
0V on Top Solder "NONET_L-01_P-001" (solid): 2.463,35.725 ccw(c4.5,35.725) 4.5,33.688 ccw(c4.5,35.725) 6.537,35.725 ccw(c4.5,35.725) 4.5,37.762 ccw(c4.5,35.725)
0V on Bottom Layer "0V_L04_P102" (solid, pour order 102): 0,0 90,0 90,50 0,50
0V on Top Layer "0V_L01_P001" (solid, pour order 1): 0,0 90,0 90,50 0,50
0V on GND "0V_L03_P056" (solid, pour order 56): 0,0 90,0 90,50 0,50

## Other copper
Top Layer:
  pour cut-out: 86.3,3 68.8,3 68.8,8 86.3,8
  pour cut-out: 66,0 66,3 90,3 90,0
PWR:
  pour cut-out: 86.3,3 68.8,3 68.8,8 86.3,8
  pour cut-out: 66,0 66,3 90,3 90,0
GND:
  pour cut-out: 86.3,3 68.8,3 68.8,8 86.3,8
  pour cut-out: 66,0 66,3 90,3 90,0
Bottom Layer:
  pour cut-out: 82.615,15.835 82.615,16.025 82.305,16.025 82.305,15.835
  pour cut-out: 82.615,13.295 82.615,13.485 82.305,13.485 82.305,13.295
  pour cut-out: 86.3,3 68.8,3 68.8,8 86.3,8
  pour cut-out: 66,0 66,3 90,3 90,0

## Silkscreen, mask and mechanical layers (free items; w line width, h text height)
Top Overlay:
  drawing of 75 lines, arcs and shapes, not listed
  text "0V" at 31.9,46.517 h1.52
  text "OUT:2" at 34.6,40.816 h1.52
  text "0V" at 46.5,39.817 h1.52
  text "3V3" at 63.1,39.517 h1.52
  text "TIA:2" at 31.7,35.9 h1.52
  text "ADC TEST" at 49.1,34.117 h1.52
  text "0V" at 63.5,31.317 h1.52
  text "0V" at 29,30.217 h1.52
  text "0V" at 31.9,22.617 h1.52
  text "OUT:1" at 34.5,16.916 h1.52
  text "TIA:1" at 31.6,9.4 h1.52
  text "0V" at 29,6.217 h1.52
Bottom Overlay:
  drawing of 73 lines, arcs and shapes, not listed
  text "STEPANCIC" at 45,47.584 h1.5 r180
  text "PB00Z0NE" at 54.9,47.584 h1.5 r180
  text "KRISTIAN" at 45,46.084 h1.5 r180
  text "ON" at 74.4,25.184 h1.52 r180
  text "OFF" at 73.7,22.684 h1.52 r180
  text "CTRL" at 72.9,20.183 h1.52 r180
  text "SYNC" at 72.7,17.583 h1.52 r180
  text "CS" at 74.6,15.183 h1.52 r180
  text "DRDY" at 72.7,12.6 h1.52 r180
  text "CLKIN" at 72.5,10.083 h1.52 r180
  text "/ZKIST" at 45,9.278 h2 r180
Bottom Solder:
  pour cut-out: 11.09,13.3 12.965,13.3 12,14.265
  pour cut-out: 11.09,37.3 12.965,37.3 12,38.265
  lines w1.5: 40.05,22.8 11.45,22.8 ccw(c11.45,20.95) 9.6,20.95 9.6,4.95 ccw(c11.45,4.95) 11.45,3.1 40.05,3.1 ccw(c40.05,4.95) 41.9,4.95 41.9,18.9 ; 40.05,27.2 11.45,27.2 cw(c11.45,29.05) 9.6,29.05 9.6,45.05 cw(c11.45,45.05) 11.45,46.9 40.05,46.9 cw(c40.05,45.05) 41.9,45.05 41.9,31
Mechanical 1:
  the board outline again, w0.5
